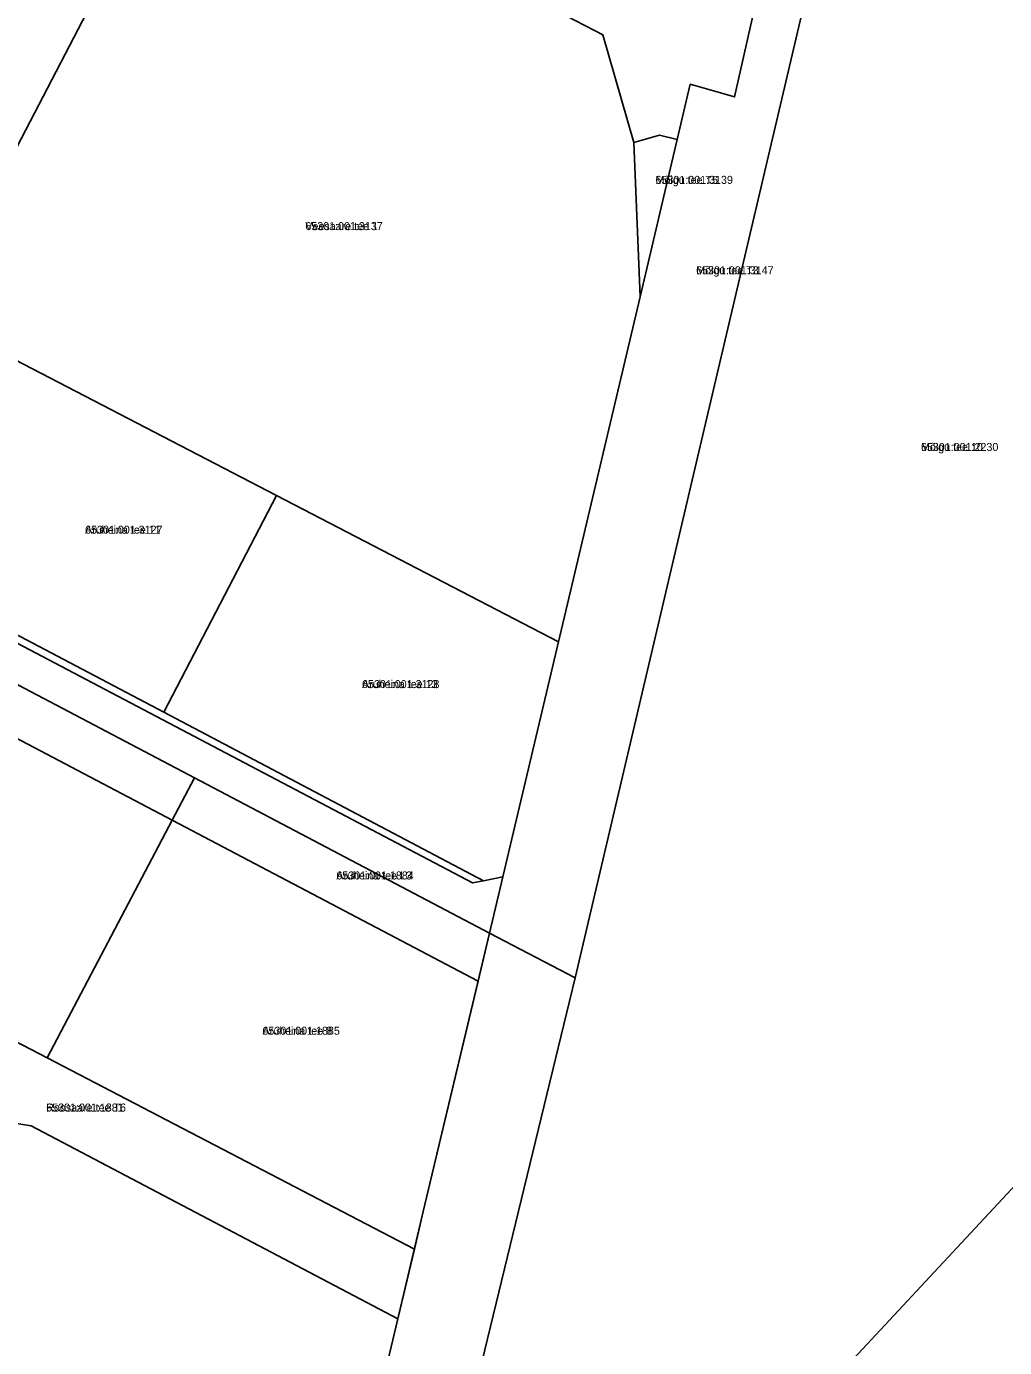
# Model space of a CAD drawing. Extents: x 543236 to 563717, y 6566033 to 6588992.
# Drawn here: x 546047.5 to 546230.8, y 6584851 to 6585098.7 of the extents above; entities that cross this region are included whole.
import ezdxf

# ---------------------------------------------------------------- set-up
doc = ezdxf.new("R2010")
doc.units = 0
for name, color, linetype in [('L_AADRESS', 7, 'Continuous'), ('PIIR', 7, 'Continuous'), ('TUNNUS', 7, 'Continuous')]:
    doc.layers.add(name, color=color, linetype=linetype)

msp = doc.modelspace()

# ---------------------------------------------------------------- linework, layer by layer
at = {"layer": 'PIIR'}
for points in [[(546175.44, 6585231.06), (546203.45, 6585188.17), (546180.22, 6585085.49), (546171.91, 6585087.85), (546169.47, 6585077.51), (546166.12, 6585078.29), (546161.32, 6585076.91), (546155.5, 6585097.14), (546145.4, 6585102.39), (546152.63, 6585116.34), (546167.49, 6585113.83), (546172.88, 6585116.73), (546156.8, 6585141.23), (546163.18, 6585145.36), (546159.25, 6585159.32), (546158.17, 6585170.55), (546159.82, 6585179.09), (546180.51, 6585207.02), (546168.38, 6585225.47)], [(545979.47, 6585188.81), (546077.67, 6585137.67), (546029.23, 6585044.54), (545992.67, 6585063.45), (545924.36, 6585098.85), (545944.99, 6585138.67), (545968.64, 6585184.3), (545975.34, 6585180.84)], [(546203.45, 6585188.17), (546211.72, 6585181.64), (546150.31, 6584920.33), (546134.3, 6584928.75), (546136.79, 6584939.31), (546147.21, 6584983.35), (546162.49, 6585047.98), (546169.47, 6585077.51), (546171.91, 6585087.85), (546180.22, 6585085.49)], [(546150.31, 6584920.33), (546211.72, 6585181.64), (546271.16, 6585077.85), (546265.77, 6585075.23), (546321.82, 6584977.11), (546108.45, 6584747.98)], [(546077.67, 6585137.67), (546145.4, 6585102.39), (546155.5, 6585097.14), (546161.32, 6585076.91), (546162.49, 6585047.98), (546147.21, 6584983.35), (546094.34, 6585010.78), (546043.67, 6585037.07), (546029.23, 6585044.54)], [(545812.07, 6585106.08), (545823.69, 6585128.22), (545833.63, 6585096.27), (545971.92, 6585023.44), (546022.77, 6584996.72), (546073.26, 6584970.13), (546133.17, 6584938.54), (546131.11, 6584938.14)], [(545805.7, 6585107.83), (545811.43, 6585104.81), (545812.07, 6585106.08), (546131.11, 6584938.14), (546133.17, 6584938.54), (546136.79, 6584939.31), (546134.3, 6584928.75), (546078.99, 6584957.84), (546025.89, 6584985.76), (545964.63, 6585017.97), (545933.81, 6585034.18), (545906.53, 6585048.53), (545879.98, 6585062.49), (545851.77, 6585077.33), (545826.71, 6585090.51), (545821.39, 6585093.3), (545808.87, 6585099.89), (545803.14, 6585102.9)], [(546161.32, 6585076.91), (546166.12, 6585078.29), (546169.47, 6585077.51), (546162.49, 6585047.98)], [(546043.67, 6585037.07), (546094.34, 6585010.78), (546073.26, 6584970.13), (546022.77, 6584996.72)], [(546094.34, 6585010.78), (546147.21, 6584983.35), (546136.79, 6584939.31), (546133.17, 6584938.54), (546073.26, 6584970.13)], [(545973.17, 6585003.34), (546000.79, 6584988.82), (545989.83, 6584967.98), (546007.36, 6584958.77), (546024.88, 6584949.55), (546035.84, 6584970.39), (546074.81, 6584949.89), (546051.4, 6584905.35), (546016.83, 6584923.27), (546026.04, 6584940.78), (546004.78, 6584951.96), (545995.57, 6584934.45), (545986.36, 6584916.93), (545979.98, 6584920.28), (545988.78, 6584937.02), (545971.26, 6584946.24), (545953.89, 6584955.38), (545957.24, 6584961.75), (545973.83, 6584953.02), (545983.04, 6584970.55), (545992.26, 6584988.07), (545971.02, 6584999.25)], [(546321.82, 6584977.11), (546366.08, 6584907.97), (546378.93, 6584888), (546108.45, 6584747.98)], [(546078.99, 6584957.84), (546134.3, 6584928.75), (546132.15, 6584919.73), (546074.81, 6584949.89)], [(546074.81, 6584949.89), (546132.15, 6584919.73), (546121.87, 6584876.54), (546120.19, 6584869.49), (546051.4, 6584905.35)], [(545942.71, 6584934.12), (545960.08, 6584924.98), (545977.61, 6584915.76), (545979.98, 6584920.28), (545986.36, 6584916.93), (546007.62, 6584905.75), (546016.83, 6584923.27), (546051.4, 6584905.35), (546120.19, 6584869.49), (546117.08, 6584856.45), (546048.37, 6584892.59), (546008.87, 6584898.97), (546001.36, 6584884.67), (545999.6, 6584882.56), (545981.16, 6584898.09), (545972.99, 6584906.68), (545961.31, 6584912.82), (545949.62, 6584918.97), (545937.97, 6584925.1)], [(546134.3, 6584928.75), (546150.31, 6584920.33), (546108.45, 6584747.98), (546093.16, 6584756.02), (546117.08, 6584856.45), (546121.87, 6584876.54)], [(546008.87, 6584898.97), (546048.37, 6584892.59), (546117.08, 6584856.45), (546093.16, 6584756.02), (545999.67, 6584805.18), (545954.65, 6584828.85), (545974.18, 6584852.2), (545979.6, 6584858.67), (545982.65, 6584862.32), (545991.13, 6584872.44), (545999.6, 6584882.56), (546001.36, 6584884.67)]]:
    msp.add_lwpolyline(points, close=True, dxfattribs=at)
msp.add_lwpolyline([(546025.89, 6584985.76), (546078.99, 6584957.84), (546074.81, 6584949.89), (546035.84, 6584970.39)], dxfattribs=at)

# ---------------------------------------------------------------- texts
at = {"layer": 'L_AADRESS'}
for s, p in [('Mõigu tee T5', (546165.39, 6585069.18)), ('Veesaare tee 1', (546099.76, 6585060.51)), ('Mõigu tee T3', (546173.01, 6585052.23)), ('Mõigu tee 10', (546215.14, 6585019.11)), ('Aruheina tee 11', (546058.48, 6585003.6)), ('Aruheina tee 13', (546110.38, 6584974.66)), ('Aruheina tee L3', (546105.57, 6584938.79)), ('Aruheina tee 8', (546091.72, 6584909.69)), ('Roosaare tee T6', (546051.2, 6584895.29))]:
    msp.add_text(s, height=1.5, dxfattribs=at).set_placement(p)
at = {"layer": 'TUNNUS'}
for s, p in [('65301:001:3139', (546165.39, 6585069.18)), ('65301:001:3137', (546099.76, 6585060.51)), ('65301:001:3147', (546173.01, 6585052.23)), ('65301:001:2230', (546215.14, 6585019.11)), ('65301:001:3127', (546058.48, 6585003.6)), ('65301:001:3128', (546110.38, 6584974.66)), ('65301:001:1884', (546105.57, 6584938.79)), ('65301:001:1885', (546091.72, 6584909.69)), ('65301:001:1881', (546051.2, 6584895.29))]:
    msp.add_text(s, height=1.5, dxfattribs=at).set_placement(p)

doc.saveas('drawing.dxf')
